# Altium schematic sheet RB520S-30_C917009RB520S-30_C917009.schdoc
size 127 x 101 mm
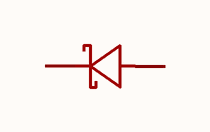
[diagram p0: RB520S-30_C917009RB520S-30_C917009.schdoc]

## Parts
D?  rb520s-30_c917009  [SOD-523_L1.2-W0.8-LS1.6-RD_1]  (value not drawn)

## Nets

Not connected (* = marked no-connect by the designer): D? 1(C) 2(A)

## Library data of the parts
D? = rb520s-30_c917009: 二极管配置:独立式;正向压降(Vf):600mV@200mA;直流反向耐压(Vr):30V;整流电流:200mA;; Manufacturer: JSMSEMI(杰盛微); AddInBom: yes; Diode Configuration: 独立式; Voltage - DC Reverse(Vr): 30V; Current - Rectified: 200mA; Reverse Leakage Current (Ir): 1uA@10V; Non-Repetitive Peak Forward Surge Current: 1A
